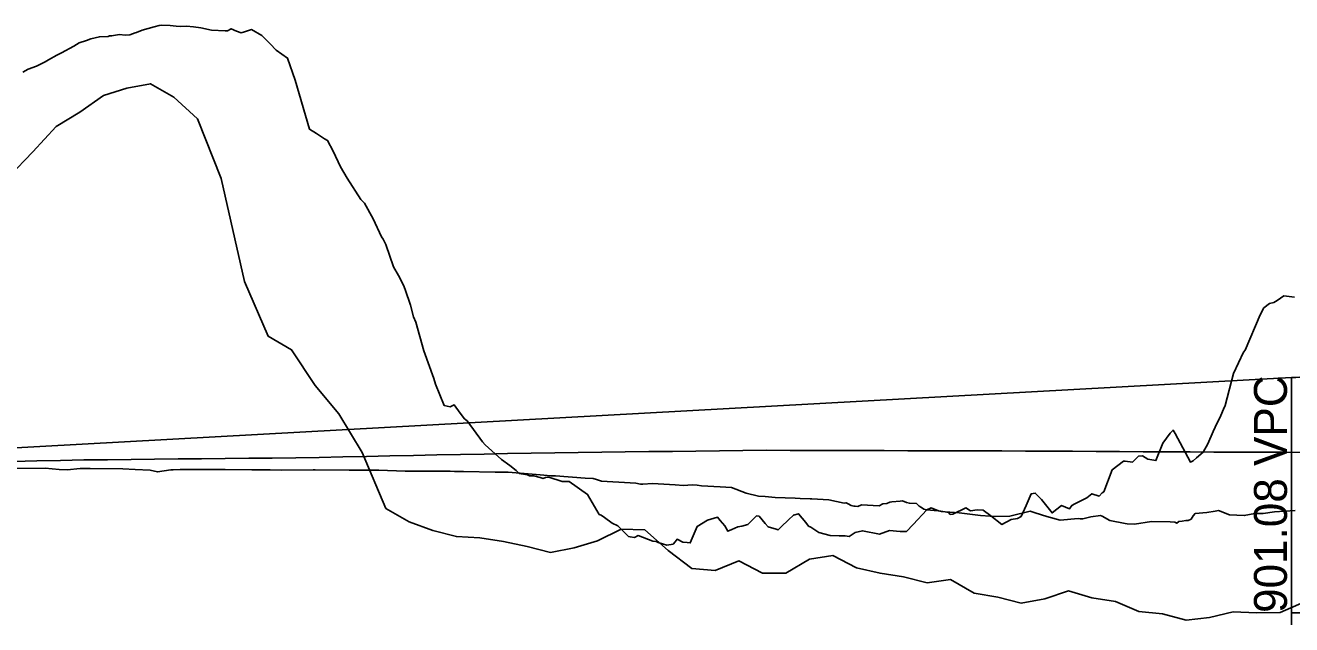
# Model space of a CAD drawing. Extents: x 1475774 to 1484571, y 1098511 to 1113011.
# Drawn here: x 1479227 to 1479496, y 1103964.1 to 1104091.5 of the extents above; entities that cross this region are included whole.
import ezdxf

# ---------------------------------------------------------------- set-up
doc = ezdxf.new("R2010")
doc.units = 0
for name, color, linetype in [('RD_DDB_PointTX', 7, 'Continuous'), ('RD_DDB_Profile_EX', 7, 'Continuous'), ('RD_DDB_Profile_PR', 7, 'Continuous'), ('RD_DDB_StripGrade', 7, 'Continuous'), ('RD_DDB_VCLbl', 7, 'Continuous'), ('RD_Sketch2', 7, 'Continuous'), ('RD_Sketch3', 7, 'Continuous')]:
    doc.layers.add(name, color=color, linetype=linetype)

msp = doc.modelspace()

# ---------------------------------------------------------------- linework, layer by layer
at = {"layer": 'RD_DDB_PointTX'}
msp.add_lwpolyline([(1479224.42, 1103998.78), (1479229.42, 1103998.91), (1479234.42, 1103999.03), (1479239.42, 1103999.12), (1479244.42, 1103999.18), (1479249.42, 1103999.23), (1479254.42, 1103999.28), (1479259.42, 1103999.34), (1479264.42, 1103999.39), (1479269.42, 1103999.44), (1479274.42, 1103999.49), (1479279.42, 1103999.53), (1479284.42, 1103999.58), (1479289.42, 1103999.66), (1479294.42, 1103999.77), (1479299.42, 1103999.88), (1479304.42, 1103999.99), (1479309.42, 1104000.09), (1479314.42, 1104000.19), (1479319.42, 1104000.29), (1479324.42, 1104000.39), (1479329.42, 1104000.49), (1479334.42, 1104000.59), (1479339.42, 1104000.66), (1479344.42, 1104000.72), (1479349.42, 1104000.77), (1479354.42, 1104000.83), (1479359.42, 1104000.89), (1479364.42, 1104000.95), (1479369.42, 1104001.01), (1479374.42, 1104001.07), (1479379.42, 1104001.12), (1479384.42, 1104001.18), (1479389.42, 1104001.17), (1479394.42, 1104001.15), (1479399.42, 1104001.14), (1479404.42, 1104001.12), (1479409.42, 1104001.11), (1479414.42, 1104001.1), (1479419.42, 1104001.08), (1479424.42, 1104001.07), (1479429.42, 1104001.05), (1479434.42, 1104001.04), (1479439.42, 1104001.02), (1479444.42, 1104000.99), (1479449.42, 1104000.96), (1479454.42, 1104000.93), (1479459.42, 1104000.91), (1479464.42, 1104000.88), (1479469.42, 1104000.85), (1479474.42, 1104000.82), (1479479.42, 1104000.79), (1479484.42, 1104000.77), (1479489.42, 1104000.76), (1479494.42, 1104000.75), (1479499.42, 1104000.74)], dxfattribs=at)
at = {"layer": 'RD_DDB_Profile_EX'}
msp.add_lwpolyline([(1479223.54, 1104059.33), (1479228.54, 1104064.6), (1479233.54, 1104069.99), (1479238.54, 1104073.02), (1479243.54, 1104076.59), (1479248.54, 1104078.16), (1479253.54, 1104079.07), (1479258.54, 1104076.21), (1479263.54, 1104071.63), (1479268.54, 1104058.93), (1479273.54, 1104037.05), (1479278.54, 1104025.43), (1479283.54, 1104022.53), (1479288.54, 1104014.98), (1479293.54, 1104008.93), (1479298.54, 1104000.71), (1479303.54, 1103988.83), (1479308.54, 1103986.01), (1479313.54, 1103984.13), (1479318.54, 1103982.83), (1479323.54, 1103982.6), (1479328.54, 1103981.77), (1479333.54, 1103980.71), (1479338.54, 1103979.48), (1479343.54, 1103980.43), (1479348.54, 1103981.92), (1479353.54, 1103984.44), (1479358.54, 1103984.25), (1479363.54, 1103979.86), (1479368.54, 1103976.04), (1479373.54, 1103975.66), (1479378.54, 1103977.66), (1479383.54, 1103975.06), (1479388.54, 1103975.09), (1479393.54, 1103978.02), (1479398.54, 1103978.84), (1479403.54, 1103976.19), (1479408.54, 1103975.06), (1479413.54, 1103974.28), (1479418.54, 1103973.02), (1479423.54, 1103973.73), (1479428.54, 1103970.82), (1479433.54, 1103969.94), (1479438.54, 1103968.72), (1479443.54, 1103969.58), (1479448.54, 1103971.29), (1479453.54, 1103969.82), (1479458.54, 1103969.07), (1479463.54, 1103966.95), (1479468.54, 1103966.4), (1479473.54, 1103965.1), (1479478.54, 1103965.67), (1479483.54, 1103966.84), (1479488.54, 1103966.62), (1479493.54, 1103966.68), (1479498.54, 1103968.89)], dxfattribs=at)
at = {"layer": 'RD_DDB_Profile_PR'}
msp.add_line((1479220.98, 1104001.5), (1479495.98, 1104016.62), dxfattribs=at)
msp.add_line((1479220.98, 1104001.5), (1479495.98, 1104016.62), dxfattribs=at)
msp.add_spline([(1479495.98, 1104016.62), (1479502.98, 1104017), (1479509.98, 1104017.37), (1479516.98, 1104017.73), (1479523.98, 1104018.07), (1479530.98, 1104018.41), (1479537.98, 1104018.73), (1479544.98, 1104019.04), (1479551.98, 1104019.34), (1479558.98, 1104019.63), (1479565.98, 1104019.91), (1479572.98, 1104020.18), (1479579.98, 1104020.44), (1479586.98, 1104020.68), (1479593.98, 1104020.92), (1479600.98, 1104021.14), (1479607.98, 1104021.35), (1479614.98, 1104021.55), (1479621.98, 1104021.74), (1479628.98, 1104021.92), (1479635.98, 1104022.08), (1479642.98, 1104022.24), (1479649.98, 1104022.38), (1479656.98, 1104022.52), (1479663.98, 1104022.64), (1479670.98, 1104022.75), (1479677.98, 1104022.85), (1479684.98, 1104022.94), (1479691.98, 1104023.01), (1479698.98, 1104023.08), (1479705.98, 1104023.13), (1479712.98, 1104023.18), (1479719.98, 1104023.21), (1479726.98, 1104023.23), (1479733.98, 1104023.24), (1479740.98, 1104023.24), (1479747.98, 1104023.23), (1479754.98, 1104023.2), (1479761.98, 1104023.17), (1479768.98, 1104023.12), (1479775.98, 1104023.06), (1479782.98, 1104022.99), (1479789.98, 1104022.91), (1479796.98, 1104022.82), (1479803.98, 1104022.72), (1479810.98, 1104022.61), (1479817.98, 1104022.48), (1479824.98, 1104022.35), (1479831.98, 1104022.2), (1479838.98, 1104022.04), (1479845.98, 1104021.87)], degree=3, dxfattribs=at)
msp.add_spline([(1479495.98, 1104016.62), (1479502.98, 1104017), (1479509.98, 1104017.37), (1479516.98, 1104017.73), (1479523.98, 1104018.07), (1479530.98, 1104018.41), (1479537.98, 1104018.73), (1479544.98, 1104019.04), (1479551.98, 1104019.34), (1479558.98, 1104019.63), (1479565.98, 1104019.91), (1479572.98, 1104020.18), (1479579.98, 1104020.44), (1479586.98, 1104020.68), (1479593.98, 1104020.92), (1479600.98, 1104021.14), (1479607.98, 1104021.35), (1479614.98, 1104021.55), (1479621.98, 1104021.74), (1479628.98, 1104021.92), (1479635.98, 1104022.08), (1479642.98, 1104022.24), (1479649.98, 1104022.38), (1479656.98, 1104022.52), (1479663.98, 1104022.64), (1479670.98, 1104022.75), (1479677.98, 1104022.85), (1479684.98, 1104022.94), (1479691.98, 1104023.01), (1479698.98, 1104023.08), (1479705.98, 1104023.13), (1479712.98, 1104023.18), (1479719.98, 1104023.21), (1479726.98, 1104023.23), (1479733.98, 1104023.24), (1479740.98, 1104023.24), (1479747.98, 1104023.23), (1479754.98, 1104023.2), (1479761.98, 1104023.17), (1479768.98, 1104023.12), (1479775.98, 1104023.06), (1479782.98, 1104022.99), (1479789.98, 1104022.91), (1479796.98, 1104022.82), (1479803.98, 1104022.72), (1479810.98, 1104022.61), (1479817.98, 1104022.48), (1479824.98, 1104022.35), (1479831.98, 1104022.2), (1479838.98, 1104022.04), (1479845.98, 1104021.87)], degree=3, dxfattribs=at)
at = {"layer": 'RD_DDB_VCLbl'}
for p, q in [((1479495.98, 1103964.12), (1479495.98, 1104016.62)), ((1479495.98, 1103966.62), (1479845.98, 1103966.62))]:
    msp.add_line(p, q, dxfattribs=at)
at = {"layer": 'RD_Sketch2'}
msp.add_lwpolyline([(1479221.59, 1103997.34), (1479231.15, 1103997.35), (1479234.12, 1103997.08), (1479235.89, 1103997.03), (1479238.6, 1103997.31), (1479240.71, 1103997.29), (1479247.7, 1103997.23), (1479250.27, 1103997.09), (1479253.5, 1103996.93), (1479255.08, 1103996.57), (1479257.91, 1103997.06), (1479258.36, 1103997.06), (1479259.83, 1103997.08), (1479263.98, 1103997.12), (1479265.44, 1103997.11), (1479269.39, 1103997.07), (1479275.07, 1103997.03), (1479278.96, 1103997), (1479281.43, 1103996.98), (1479288.1, 1103997.02), (1479288.52, 1103997.02), (1479295.77, 1103996.94), (1479298.08, 1103996.94), (1479302.08, 1103996.94), (1479307.64, 1103996.77), (1479308.99, 1103996.73), (1479317.2, 1103996.71), (1479318.14, 1103996.7), (1479320.03, 1103996.7), (1479326.76, 1103996.56), (1479328.98, 1103996.51), (1479329.57, 1103996.5), (1479336.33, 1103995.96), (1479338.62, 1103995.78), (1479339.17, 1103995.78), (1479339.58, 1103995.75), (1479345.89, 1103995.28), (1479347.58, 1103995.16), (1479348.29, 1103994.99), (1479349.39, 1103994.63), (1479355.45, 1103994.25), (1479356.67, 1103994.17), (1479357.63, 1103994.01), (1479358.13, 1103993.98), (1479360.22, 1103994.09), (1479365.01, 1103993.82), (1479366.81, 1103993.72), (1479368.6, 1103993.81), (1479369.66, 1103993.76), (1479370.59, 1103993.66), (1479374.57, 1103993.42), (1479376.96, 1103993.29), (1479380.09, 1103992.08), (1479382.75, 1103991.44), (1479384.13, 1103991.33), (1479386.29, 1103991.17), (1479390.53, 1103991.02), (1479391.56, 1103990.94), (1479393.7, 1103990.89), (1479394.05, 1103990.88), (1479397.69, 1103990.63), (1479400.91, 1103989.95), (1479401.31, 1103990.04), (1479401.76, 1103989.82), (1479402.42, 1103989.43), (1479402.96, 1103989.33), (1479403.26, 1103989.3), (1479403.84, 1103989.24), (1479404.58, 1103989.62), (1479408.37, 1103989.35), (1479409.15, 1103989.77), (1479409.97, 1103989.9), (1479410.63, 1103990.14), (1479411.07, 1103990.22), (1479412.82, 1103990.39), (1479413.29, 1103990.43), (1479414.19, 1103990.12), (1479414.79, 1103989.93), (1479416.3, 1103989.84), (1479416.83, 1103989.33), (1479417.33, 1103989.01), (1479417.83, 1103988.69), (1479418.38, 1103988.55), (1479420.88, 1103988.35), (1479421.51, 1103988.2), (1479422.38, 1103988.13), (1479425.33, 1103987.88), (1479429.91, 1103987.33), (1479431.94, 1103987.17), (1479433.13, 1103987.08), (1479436.13, 1103987.19), (1479440.4, 1103988.22), (1479441.5, 1103987.87), (1479443.96, 1103987.1), (1479446.78, 1103986.34), (1479450.63, 1103986.67), (1479451.07, 1103986.64), (1479451.6, 1103986.62), (1479453.35, 1103987.03), (1479455.34, 1103987.31), (1479455.75, 1103987.15), (1479457.36, 1103986.29), (1479460.63, 1103985.62), (1479461.04, 1103985.54), (1479462.62, 1103985.47), (1479466.18, 1103986.05), (1479470.19, 1103985.95), (1479471.13, 1103985.92), (1479471.58, 1103985.68), (1479472.03, 1103986.05), (1479472.74, 1103986.11), (1479473.52, 1103986.24), (1479473.99, 1103986.23), (1479474.6, 1103986.57), (1479475.09, 1103987.27), (1479475.46, 1103987.73), (1479477.97, 1103987.98), (1479479.75, 1103988.27), (1479480.41, 1103988.38), (1479482.81, 1103987.45), (1479485.9, 1103987.29), (1479488.16, 1103987.77), (1479489.31, 1103987.76), (1479489.93, 1103987.77), (1479492.35, 1103988.11), (1479496.73, 1103988.41)], dxfattribs=at)
at = {"layer": 'RD_Sketch3'}
msp.add_lwpolyline([(1479226.42, 1104081.54), (1479227.6, 1104082.18), (1479229.33, 1104082.84), (1479230.04, 1104083.15), (1479231.15, 1104083.74), (1479231.91, 1104084.14), (1479233.66, 1104085.15), (1479234.07, 1104085.38), (1479234.66, 1104085.65), (1479237.29, 1104087.08), (1479238.38, 1104087.73), (1479239.98, 1104088.24), (1479240.91, 1104088.63), (1479242.69, 1104089.07), (1479244.53, 1104089.14), (1479244.84, 1104089.22), (1479245.3, 1104089.25), (1479247, 1104089.56), (1479248.16, 1104089.41), (1479249.15, 1104089.49), (1479250.27, 1104089.87), (1479250.61, 1104089.99), (1479251.79, 1104090.46), (1479254.32, 1104091.17), (1479255.41, 1104091.47), (1479255.92, 1104091.49), (1479257.77, 1104091.44), (1479259.04, 1104091.32), (1479259.93, 1104091.27), (1479261.23, 1104091.32), (1479262.67, 1104091.2), (1479264.24, 1104090.92), (1479266.53, 1104090.43), (1479269.39, 1104090.33), (1479269.93, 1104090.31), (1479270.7, 1104090.76), (1479271.83, 1104090.21), (1479272.85, 1104089.92), (1479273.56, 1104090.09), (1479275.01, 1104090.59), (1479277.22, 1104089.35), (1479278.96, 1104087.56), (1479280.25, 1104086.23), (1479282.66, 1104084.52), (1479284.31, 1104079.83), (1479287.36, 1104069.4), (1479288.8, 1104068.47), (1479290.5, 1104067.33), (1479291.17, 1104067), (1479292.36, 1104064.76), (1479293.93, 1104061.45), (1479295.31, 1104059.03), (1479298.27, 1104054.49), (1479298.99, 1104053.69), (1479300.85, 1104050.34), (1479302.63, 1104046.56), (1479303.01, 1104046.04), (1479303.55, 1104044.91), (1479305.16, 1104040.2), (1479306.27, 1104038.34), (1479307.31, 1104036.28), (1479307.64, 1104035.35), (1479308.82, 1104032), (1479309.46, 1104029.55), (1479309.91, 1104028.4), (1479311.62, 1104022.34), (1479313.77, 1104016.46), (1479314.09, 1104015.21), (1479315.92, 1104010.72), (1479317.2, 1104010.44), (1479318.08, 1104010.83), (1479319.36, 1104009.08), (1479320.23, 1104007.9), (1479320.83, 1104007.42), (1479324.12, 1104002.95), (1479324.62, 1104002.31), (1479326.76, 1104000.42), (1479328.11, 1103999.22), (1479329.88, 1103997.92), (1479331.21, 1103996.91), (1479331.9, 1103996.22), (1479333.67, 1103995.98), (1479334.1, 1103995.77), (1479334.99, 1103995.76), (1479336.33, 1103995.38), (1479336.96, 1103995.2), (1479337.45, 1103995.4), (1479338.18, 1103995.48), (1479341.03, 1103994.55), (1479341.83, 1103994.53), (1479342.49, 1103994.52), (1479346.4, 1103991.81), (1479348.9, 1103987.56), (1479349.32, 1103987.42), (1479350.03, 1103986.93), (1479351.64, 1103985.71), (1479352.84, 1103985.11), (1479355.11, 1103982.88), (1479355.45, 1103982.82), (1479356.4, 1103982.66), (1479357.18, 1103983.05), (1479360.24, 1103981.85), (1479360.99, 1103981.83), (1479361.37, 1103981.6), (1479363.26, 1103981.02), (1479364.58, 1103981.22), (1479365.01, 1103981.76), (1479365.42, 1103982.26), (1479366.61, 1103981.68), (1479367.57, 1103981.62), (1479368.23, 1103981.51), (1479369.72, 1103985.02), (1479371.89, 1103986.32), (1479374.02, 1103986.94), (1479374.57, 1103986.29), (1479375.54, 1103985.15), (1479376.17, 1103983.97), (1479377.07, 1103984.33), (1479378.32, 1103984.9), (1479379.19, 1103985.06), (1479380.47, 1103985.41), (1479382.3, 1103987.28), (1479382.85, 1103987.21), (1479384.13, 1103985.65), (1479384.77, 1103984.88), (1479386.5, 1103984.43), (1479386.92, 1103984.27), (1479387.52, 1103984.88), (1479389.07, 1103986.43), (1479390.16, 1103987.39), (1479391.22, 1103987.71), (1479392.74, 1103985.86), (1479393.37, 1103985.07), (1479393.81, 1103984.81), (1479395.52, 1103983.74), (1479397.96, 1103983.04), (1479399.82, 1103983), (1479401.13, 1103983.03), (1479401.97, 1103982.88), (1479403.26, 1103983.72), (1479404.79, 1103984.09), (1479408.45, 1103983.37), (1479410.57, 1103984.16), (1479412.82, 1103983.94), (1479414.14, 1103983.92), (1479415.6, 1103985.39), (1479418.46, 1103988.5), (1479419.42, 1103988.93), (1479420.98, 1103988.32), (1479422.38, 1103988.07), (1479423.1, 1103987.94), (1479423.47, 1103987.56), (1479423.99, 1103987.59), (1479426.77, 1103988.92), (1479427.77, 1103988.35), (1479429.18, 1103988.53), (1479430.43, 1103988.45), (1479432.06, 1103987.25), (1479434.38, 1103985.42), (1479436.36, 1103986.45), (1479437.76, 1103986.72), (1479438.51, 1103987.12), (1479439.56, 1103989.47), (1479440.66, 1103991.96), (1479441.5, 1103992.1), (1479442.81, 1103990.73), (1479445.1, 1103987.88), (1479447.1, 1103989.42), (1479448.77, 1103988.71), (1479449.25, 1103989.48), (1479449.93, 1103989.81), (1479451.07, 1103990.38), (1479452.44, 1103991.08), (1479453.55, 1103991.95), (1479455.11, 1103991.44), (1479455.7, 1103992.15), (1479456.11, 1103992.36), (1479457.84, 1103997.06), (1479460.29, 1103998.9), (1479460.63, 1103998.85), (1479462.14, 1103998.63), (1479463.46, 1103999.91), (1479464.29, 1104000.03), (1479465.46, 1103999.27), (1479467.13, 1103999.01), (1479468.58, 1104002.71), (1479470.19, 1104004.81), (1479470.8, 1104005.49), (1479471.23, 1104004.78), (1479474.48, 1103998.67), (1479475.03, 1103998.91), (1479475.8, 1103999.59), (1479477.17, 1104000.78), (1479478.15, 1104002.52), (1479479.32, 1104005.2), (1479479.75, 1104006.08), (1479480.96, 1104008.57), (1479481.47, 1104009.95), (1479481.83, 1104010.7), (1479483.62, 1104017.53), (1479485.76, 1104022.02), (1479486.12, 1104022.45), (1479489.31, 1104029.95), (1479490.06, 1104031.45), (1479491.28, 1104032.36), (1479492.2, 1104032.61), (1479492.87, 1104033.02), (1479494.35, 1104033.98), (1479496.55, 1104033.7)], dxfattribs=at)

# ---------------------------------------------------------------- texts
at = {"layer": 'RD_DDB_StripGrade'}
msp.add_text('901.08 VPC', height=7, rotation=90, dxfattribs=at).set_placement((1479494.98, 1103966.62))

doc.saveas('drawing.dxf')
